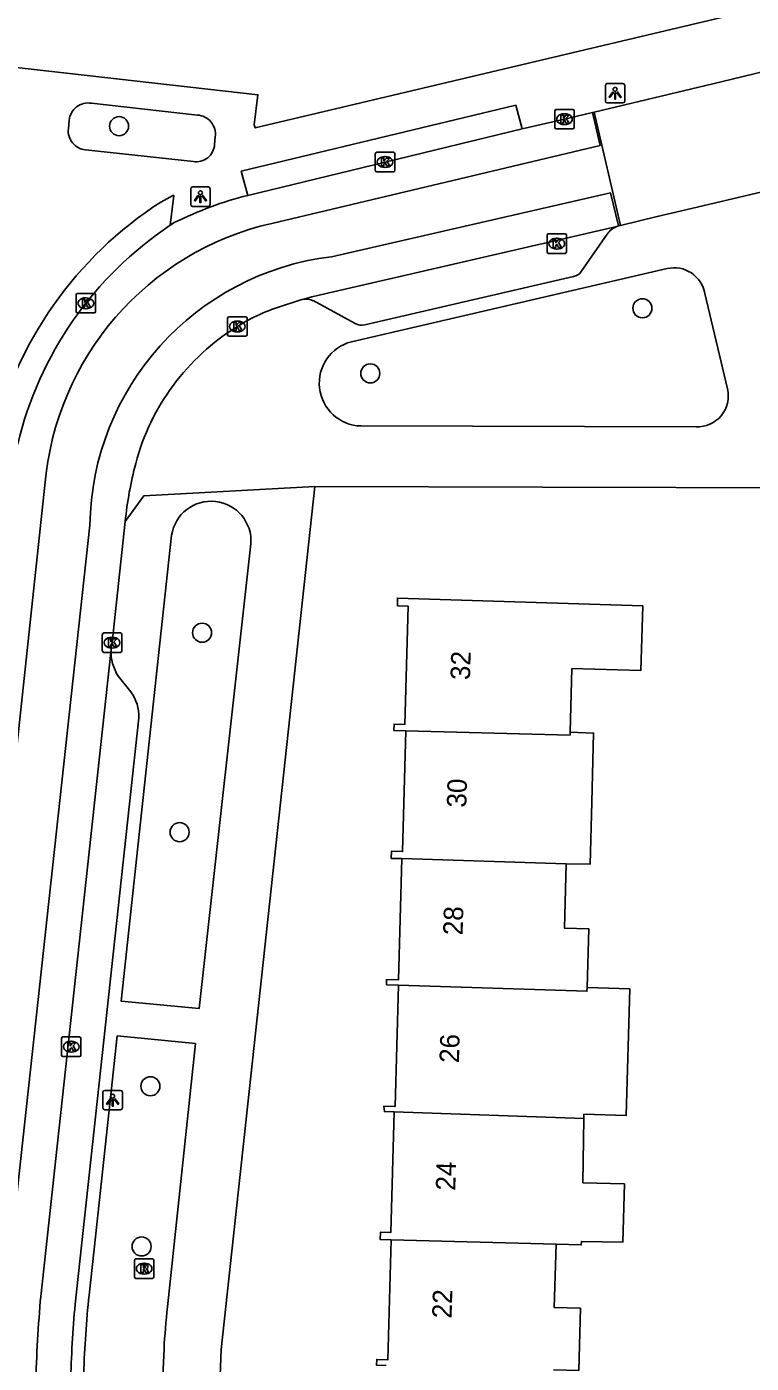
# Model space of a CAD drawing. Extents: x 162082 to 163393, y 388091 to 388632.
# Drawn here: x 162912.2 to 162949.4, y 388192.6 to 388261.2 of the extents above; entities that cross this region are included whole.
import ezdxf

# ---------------------------------------------------------------- set-up
doc = ezdxf.new("R2010")
doc.units = 0
for name, color, linetype in [('IMGEO_Boom', 7, 'Continuous'), ('IMGEO_Kolk', 7, 'Continuous'), ('IMGEO_Lichtpunt', 7, 'Continuous'), ('IMGEO_Muur', 7, 'Continuous'), ('IMGEO_Pand', 7, 'Continuous'), ('IMGEO_Pand_nummerreeks', 7, 'Continuous'), ('IMGEO_Rijbaan_lokaal_gesloten', 7, 'Continuous'), ('IMGEO_Rioolput', 7, 'Continuous'), ('IMGEO_Voetpad_open', 7, 'Continuous')]:
    doc.layers.add(name, color=color, linetype=linetype)

msp = doc.modelspace()

# ---------------------------------------------------------------- linework, layer by layer
at = {"layer": 'IMGEO_Boom'}
for centre in [(162916.912, 388256.097), (162943.781, 388246.745), (162929.812, 388243.401), (162921.173, 388230.086), (162920.021, 388219.843), (162918.519, 388206.794), (162918.07, 388198.567)]:
    msp.add_circle(centre, 0.489, dxfattribs=at)
at = {"layer": 'IMGEO_Kolk'}
for p, q in [((162939.28, 388256.031), (162939.28, 388256.883)), ((162939.355, 388256.957), (162940.207, 388256.957)), ((162939.768, 388256.737), (162939.793, 388256.737)), ((162940.281, 388256.883), (162940.281, 388256.031)), ((162940.207, 388255.957), (162939.355, 388255.957)), ((162939.791, 388256.177), (162939.766, 388256.177)), ((162930.068, 388253.829), (162930.068, 388254.681)), ((162930.143, 388254.755), (162930.995, 388254.755)), ((162930.556, 388254.535), (162930.581, 388254.535)), ((162931.069, 388254.681), (162931.069, 388253.829)), ((162930.995, 388253.755), (162930.143, 388253.755)), ((162930.579, 388253.975), (162930.554, 388253.975)), ((162938.886, 388249.64), (162938.886, 388250.492)), ((162938.961, 388250.566), (162939.813, 388250.566)), ((162939.374, 388250.346), (162939.399, 388250.346)), ((162939.887, 388250.492), (162939.887, 388249.64)), ((162939.813, 388249.566), (162938.961, 388249.566)), ((162939.397, 388249.786), (162939.372, 388249.786)), ((162914.78, 388247.503), (162915.632, 388247.503)), ((162914.705, 388246.577), (162914.705, 388247.429)), ((162915.193, 388247.283), (162915.218, 388247.283)), ((162915.706, 388247.429), (162915.706, 388246.577)), ((162915.632, 388246.503), (162914.78, 388246.503)), ((162915.216, 388246.723), (162915.191, 388246.723)), ((162922.482, 388245.384), (162922.482, 388246.236)), ((162922.557, 388246.31), (162923.409, 388246.31)), ((162923.483, 388246.236), (162923.483, 388245.384)), ((162922.993, 388245.53), (162922.968, 388245.53)), ((162922.97, 388246.09), (162922.995, 388246.09)), ((162923.409, 388245.31), (162922.557, 388245.31)), ((162916.051, 388229.148), (162916.051, 388230)), ((162916.126, 388230.074), (162916.978, 388230.074)), ((162916.539, 388229.854), (162916.564, 388229.854)), ((162917.052, 388230), (162917.052, 388229.148)), ((162916.978, 388229.074), (162916.126, 388229.074)), ((162916.562, 388229.294), (162916.537, 388229.294)), ((162913.954, 388208.399), (162913.954, 388209.251)), ((162914.029, 388209.325), (162914.881, 388209.325)), ((162914.442, 388209.105), (162914.467, 388209.105)), ((162914.955, 388209.251), (162914.955, 388208.399)), ((162914.465, 388208.545), (162914.44, 388208.545)), ((162914.881, 388208.325), (162914.029, 388208.325))]:
    msp.add_line(p, q, dxfattribs=at)
for points in [[(162939.28, 388256.031), (162939.28, 388256.883)], [(162939.355, 388256.957), (162940.207, 388256.957)], [(162939.601, 388256.657), (162939.724, 388256.657), (162939.724, 388256.506), (162939.854, 388256.657), (162940.018, 388256.657), (162939.872, 388256.506), (162940.025, 388256.257), (162939.873, 388256.257), (162939.788, 388256.421), (162939.724, 388256.354), (162939.724, 388256.257), (162939.601, 388256.257), (162939.601, 388256.657)], [(162940.281, 388256.883), (162940.281, 388256.031)], [(162940.207, 388255.957), (162939.355, 388255.957)], [(162930.068, 388253.829), (162930.068, 388254.681)], [(162930.143, 388254.755), (162930.995, 388254.755)], [(162930.389, 388254.455), (162930.512, 388254.455), (162930.512, 388254.304), (162930.642, 388254.455), (162930.806, 388254.455), (162930.66, 388254.304), (162930.813, 388254.055), (162930.661, 388254.055), (162930.576, 388254.219), (162930.512, 388254.152), (162930.512, 388254.055), (162930.389, 388254.055), (162930.389, 388254.455)], [(162931.069, 388254.681), (162931.069, 388253.829)], [(162930.995, 388253.755), (162930.143, 388253.755)], [(162938.886, 388249.64), (162938.886, 388250.492)], [(162938.961, 388250.566), (162939.813, 388250.566)], [(162939.207, 388250.266), (162939.33, 388250.266), (162939.33, 388250.115), (162939.46, 388250.266), (162939.624, 388250.266), (162939.478, 388250.115), (162939.631, 388249.866), (162939.479, 388249.866), (162939.394, 388250.03), (162939.33, 388249.963), (162939.33, 388249.866), (162939.207, 388249.866), (162939.207, 388250.266)], [(162939.887, 388250.492), (162939.887, 388249.64)], [(162939.813, 388249.566), (162938.961, 388249.566)], [(162914.78, 388247.503), (162915.632, 388247.503)], [(162914.705, 388246.577), (162914.705, 388247.429)], [(162915.026, 388247.203), (162915.149, 388247.203), (162915.149, 388247.052), (162915.279, 388247.203), (162915.443, 388247.203), (162915.297, 388247.052), (162915.45, 388246.803), (162915.298, 388246.803), (162915.213, 388246.967), (162915.149, 388246.9), (162915.149, 388246.803), (162915.026, 388246.803), (162915.026, 388247.203)], [(162915.706, 388247.429), (162915.706, 388246.577)], [(162915.632, 388246.503), (162914.78, 388246.503)], [(162922.482, 388245.384), (162922.482, 388246.236)], [(162922.557, 388246.31), (162923.409, 388246.31)], [(162923.483, 388246.236), (162923.483, 388245.384)], [(162922.803, 388246.01), (162922.926, 388246.01), (162922.926, 388245.859), (162923.056, 388246.01), (162923.22, 388246.01), (162923.074, 388245.859), (162923.227, 388245.61), (162923.075, 388245.61), (162922.99, 388245.774), (162922.926, 388245.707), (162922.926, 388245.61), (162922.803, 388245.61), (162922.803, 388246.01)], [(162923.409, 388245.31), (162922.557, 388245.31)], [(162916.051, 388229.148), (162916.051, 388230)], [(162916.126, 388230.074), (162916.978, 388230.074)], [(162916.372, 388229.774), (162916.495, 388229.774), (162916.495, 388229.623), (162916.625, 388229.774), (162916.789, 388229.774), (162916.643, 388229.623), (162916.796, 388229.374), (162916.644, 388229.374), (162916.559, 388229.538), (162916.495, 388229.471), (162916.495, 388229.374), (162916.372, 388229.374), (162916.372, 388229.774)], [(162917.052, 388230), (162917.052, 388229.148)], [(162916.978, 388229.074), (162916.126, 388229.074)], [(162913.954, 388208.399), (162913.954, 388209.251)], [(162914.029, 388209.325), (162914.881, 388209.325)], [(162914.955, 388209.251), (162914.955, 388208.399)], [(162914.275, 388209.025), (162914.398, 388209.025), (162914.398, 388208.874), (162914.528, 388209.025), (162914.692, 388209.025), (162914.546, 388208.874), (162914.699, 388208.625), (162914.547, 388208.625), (162914.462, 388208.789), (162914.398, 388208.722), (162914.398, 388208.625), (162914.275, 388208.625), (162914.275, 388209.025)], [(162914.881, 388208.325), (162914.029, 388208.325)]]:
    msp.add_lwpolyline(points, dxfattribs=at)
for centre, start, end in [((162939.357, 388256.881), 91.55205, 178.44795), ((162939.357, 388256.881), 91.55205, 178.44795), ((162940.205, 388256.881), 1.55205, 88.44795), ((162940.205, 388256.881), 1.55205, 88.44795), ((162939.357, 388256.033), 181.55205, 268.44795), ((162939.357, 388256.033), 181.55205, 268.44795), ((162940.205, 388256.033), 271.55205, 358.44795), ((162940.205, 388256.033), 271.55205, 358.44795), ((162930.145, 388254.679), 91.55205, 178.44795), ((162930.145, 388254.679), 91.55205, 178.44795), ((162930.993, 388254.679), 1.55205, 88.44795), ((162930.993, 388254.679), 1.55205, 88.44795), ((162930.145, 388253.831), 181.55205, 268.44795), ((162930.145, 388253.831), 181.55205, 268.44795), ((162930.993, 388253.831), 271.55205, 358.44795), ((162930.993, 388253.831), 271.55205, 358.44795), ((162938.963, 388250.49), 91.55205, 178.44795), ((162938.963, 388250.49), 91.55205, 178.44795), ((162939.811, 388250.49), 1.55205, 88.44795), ((162939.811, 388250.49), 1.55205, 88.44795), ((162938.963, 388249.642), 181.55205, 268.44795), ((162938.963, 388249.642), 181.55205, 268.44795), ((162939.811, 388249.642), 271.55205, 358.44795), ((162939.811, 388249.642), 271.55205, 358.44795), ((162914.782, 388247.427), 91.55205, 178.44795), ((162914.782, 388247.427), 91.55205, 178.44795), ((162915.63, 388247.427), 1.55205, 88.44795), ((162915.63, 388247.427), 1.55205, 88.44795), ((162914.782, 388246.579), 181.55205, 268.44795), ((162914.782, 388246.579), 181.55205, 268.44795), ((162915.63, 388246.579), 271.55205, 358.44795), ((162915.63, 388246.579), 271.55205, 358.44795), ((162922.559, 388246.234), 91.55205, 178.44795), ((162922.559, 388246.234), 91.55205, 178.44795), ((162923.407, 388246.234), 1.55205, 88.44795), ((162923.407, 388246.234), 1.55205, 88.44795), ((162922.559, 388245.386), 181.55205, 268.44795), ((162922.559, 388245.386), 181.55205, 268.44795), ((162923.407, 388245.386), 271.55205, 358.44795), ((162923.407, 388245.386), 271.55205, 358.44795), ((162916.128, 388229.998), 91.55205, 178.44795), ((162916.128, 388229.998), 91.55205, 178.44795), ((162916.976, 388229.998), 1.55205, 88.44795), ((162916.976, 388229.998), 1.55205, 88.44795), ((162916.128, 388229.15), 181.55205, 268.44795), ((162916.128, 388229.15), 181.55205, 268.44795), ((162916.976, 388229.15), 271.55205, 358.44795), ((162916.976, 388229.15), 271.55205, 358.44795), ((162914.031, 388209.249), 91.55205, 178.44795), ((162914.031, 388209.249), 91.55205, 178.44795), ((162914.879, 388209.249), 1.55205, 88.44795), ((162914.879, 388209.249), 1.55205, 88.44795), ((162914.031, 388208.401), 181.55205, 268.44795), ((162914.031, 388208.401), 181.55205, 268.44795), ((162914.879, 388208.401), 271.55205, 358.44795), ((162914.879, 388208.401), 271.55205, 358.44795)]:
    msp.add_arc(centre, 0.0765, start, end, dxfattribs=at)
for centre, major_axis, ratio, start_param, end_param in [((162939.767, 388256.457), (-0.387, 0.002), 0.722429, 4.712389, 7.853982), ((162939.792, 388256.457), (-0.39, 0.002), 0.717154, 1.570796, 4.712389), ((162930.555, 388254.255), (-0.387, 0.002), 0.722429, 4.712389, 7.853982), ((162930.58, 388254.255), (-0.39, 0.002), 0.717154, 1.570796, 4.712389), ((162939.373, 388250.066), (-0.387, 0.002), 0.722429, 4.712389, 7.853982), ((162939.398, 388250.066), (-0.39, 0.002), 0.717154, 1.570796, 4.712389), ((162915.192, 388247.003), (-0.387, 0.002), 0.722429, 4.712389, 7.853982), ((162915.217, 388247.003), (-0.39, 0.002), 0.717154, 1.570796, 4.712389), ((162922.969, 388245.81), (-0.387, 0.002), 0.722429, 4.712389, 7.853982), ((162922.994, 388245.81), (-0.39, 0.002), 0.717154, 1.570796, 4.712389), ((162916.538, 388229.574), (-0.387, 0.002), 0.722429, 4.712389, 7.853982), ((162916.563, 388229.574), (-0.39, 0.002), 0.717154, 1.570796, 4.712389), ((162914.441, 388208.825), (-0.387, 0.002), 0.722429, 4.712389, 7.853982), ((162914.466, 388208.825), (-0.39, 0.002), 0.717154, 1.570796, 4.712389)]:
    msp.add_ellipse(centre, major_axis=major_axis, ratio=ratio, start_param=start_param, end_param=end_param, dxfattribs=at)
at = {"layer": 'IMGEO_Lichtpunt'}
for p, q in [((162941.882, 388258.192), (162941.882, 388257.385)), ((162941.882, 388258.192), (162941.882, 388257.385)), ((162942.784, 388258.287), (162941.976, 388258.287)), ((162942.784, 388258.287), (162941.976, 388258.287)), ((162942.878, 388257.385), (162942.878, 388258.192)), ((162942.878, 388257.385), (162942.878, 388258.192)), ((162941.976, 388257.291), (162942.784, 388257.291)), ((162941.976, 388257.291), (162942.784, 388257.291)), ((162921.491, 388252.974), (162920.683, 388252.974)), ((162921.491, 388252.974), (162920.683, 388252.974)), ((162920.589, 388252.879), (162920.589, 388252.072)), ((162920.589, 388252.879), (162920.589, 388252.072)), ((162921.585, 388252.072), (162921.585, 388252.879)), ((162921.585, 388252.072), (162921.585, 388252.879)), ((162920.683, 388251.978), (162921.491, 388251.978)), ((162920.683, 388251.978), (162921.491, 388251.978)), ((162916.085, 388206.486), (162916.085, 388205.679)), ((162916.085, 388206.486), (162916.085, 388205.679)), ((162916.987, 388206.581), (162916.179, 388206.581)), ((162916.987, 388206.581), (162916.179, 388206.581)), ((162917.081, 388205.679), (162917.081, 388206.486)), ((162917.081, 388205.679), (162917.081, 388206.486)), ((162916.179, 388205.585), (162916.987, 388205.585)), ((162916.179, 388205.585), (162916.987, 388205.585))]:
    msp.add_line(p, q, dxfattribs=at)
for points in [[(162942.256, 388257.856), (162942.295, 388257.828), (162942.107, 388257.566), (162942.069, 388257.593), (162942.256, 388257.856)], [(162942.358, 388257.808), (162942.405, 388257.808), (162942.405, 388257.486), (162942.358, 388257.486), (162942.358, 388257.808)], [(162942.468, 388257.828), (162942.506, 388257.855), (162942.693, 388257.593), (162942.654, 388257.565), (162942.468, 388257.828)], [(162920.963, 388252.543), (162921.002, 388252.515), (162920.814, 388252.253), (162920.776, 388252.28), (162920.963, 388252.543)], [(162921.065, 388252.495), (162921.112, 388252.495), (162921.112, 388252.173), (162921.065, 388252.173), (162921.065, 388252.495)], [(162921.175, 388252.515), (162921.213, 388252.542), (162921.4, 388252.28), (162921.361, 388252.252), (162921.175, 388252.515)], [(162916.459, 388206.15), (162916.498, 388206.122), (162916.31, 388205.86), (162916.272, 388205.887), (162916.459, 388206.15)], [(162916.561, 388206.102), (162916.608, 388206.102), (162916.608, 388205.78), (162916.561, 388205.78), (162916.561, 388206.102)], [(162916.671, 388206.122), (162916.709, 388206.149), (162916.896, 388205.887), (162916.857, 388205.859), (162916.671, 388206.122)]]:
    msp.add_lwpolyline(points, dxfattribs=at)
for centre in [(162942.381, 388257.99), (162921.088, 388252.677), (162916.584, 388206.284)]:
    msp.add_circle(centre, 0.0994, dxfattribs=at)
for centre, start, end in [((162941.976, 388258.192), 90, 180), ((162941.976, 388258.192), 90, 180), ((162942.784, 388258.192), 0, 90), ((162942.784, 388258.192), 0, 90), ((162941.976, 388257.385), 180, 270), ((162941.976, 388257.385), 180, 270), ((162942.784, 388257.385), 270, 0), ((162942.784, 388257.385), 270, 360), ((162920.683, 388252.879), 90, 180), ((162920.683, 388252.879), 90, 180), ((162921.491, 388252.879), 0, 90), ((162921.491, 388252.879), 0, 90), ((162920.683, 388252.072), 180, 270), ((162920.683, 388252.072), 180, 270), ((162921.491, 388252.072), 270, 0), ((162921.491, 388252.072), 270, 360), ((162916.179, 388206.486), 90, 180), ((162916.179, 388206.486), 90, 180), ((162916.987, 388206.486), 0, 90), ((162916.987, 388206.486), 0, 90), ((162916.179, 388205.679), 180, 270), ((162916.179, 388205.679), 180, 270), ((162916.987, 388205.679), 270, 0), ((162916.987, 388205.679), 270, 360)]:
    msp.add_arc(centre, 0.0946, start, end, dxfattribs=at)
at = {"layer": 'IMGEO_Muur'}
msp.add_lwpolyline([(162938.65, 388237.56), (162952.361, 388237.528)], dxfattribs=at)
at = {"layer": 'IMGEO_Pand'}
for points in [[(162931.642, 388225.045), (162931.025, 388225.07), (162931.029, 388225.391), (162931.587, 388225.376), (162931.754, 388231.453), (162931.211, 388231.461), (162931.207, 388231.86), (162943.8, 388231.472), (162943.708, 388228.144), (162940.164, 388228.241), (162940.074, 388224.983)], [(162931.426, 388218.487), (162930.882, 388218.495), (162930.891, 388218.864), (162931.472, 388218.848), (162931.642, 388225.045)], [(162940.074, 388224.983), (162940.07, 388224.831), (162931.642, 388225.045)], [(162940.074, 388224.983), (162941.279, 388224.927), (162941.182, 388221.388), (162941.094, 388218.191), (162939.868, 388218.224)], [(162931.254, 388211.984), (162930.648, 388212.004), (162930.648, 388212.273), (162931.255, 388212.257), (162931.426, 388218.487)], [(162931.426, 388218.487), (162939.868, 388218.224)], [(162939.868, 388218.224), (162939.778, 388214.914), (162941.023, 388214.879), (162940.94, 388211.859)], [(162931.038, 388205.483), (162930.534, 388205.497), (162930.508, 388205.777), (162931.084, 388205.761), (162931.254, 388211.984)], [(162940.94, 388211.859), (162940.935, 388211.676), (162931.254, 388211.984)], [(162940.94, 388211.859), (162943.134, 388211.791), (162942.956, 388205.289), (162940.775, 388205.355), (162940.769, 388205.136)], [(162930.879, 388198.904), (162930.319, 388198.919), (162930.329, 388199.301), (162930.868, 388199.286), (162931.038, 388205.483)], [(162931.038, 388205.483), (162940.769, 388205.136)], [(162940.769, 388205.136), (162940.73, 388201.838), (162942.86, 388201.78), (162942.778, 388198.79), (162940.648, 388198.828), (162940.643, 388198.646), (162939.348, 388198.681)], [(162930.625, 388192.454), (162930.137, 388192.468), (162930.145, 388192.767), (162930.711, 388192.752), (162930.879, 388198.904)], [(162939.348, 388198.681), (162930.879, 388198.904)], [(162939.348, 388198.681), (162939.259, 388195.428), (162940.603, 388195.392), (162940.516, 388192.195), (162939.221, 388192.23)]]:
    msp.add_lwpolyline(points, dxfattribs=at)
at = {"layer": 'IMGEO_Rijbaan_lokaal_gesloten'}
for points in [[(162941.305, 388256.821), (162947.83, 388258.381), (162950.712, 388259.07)], [(162924.749, 388251.106), (162941.607, 388255.112), (162941.219, 388256.801)], [(162937.611, 388255.956), (162939.781, 388256.457), (162941.219, 388256.801)], [(162941.219, 388256.801), (162941.305, 388256.821)], [(162941.305, 388256.821), (162942.66, 388251.004)], [(162937.611, 388255.956), (162930.569, 388254.255), (162923.529, 388252.54)], [(162942.66, 388251.004), (162944.548, 388251.451), (162946.007, 388251.799), (162949.926, 388252.732), (162954.592, 388253.843)], [(162942.55, 388250.976), (162942.15, 388252.668), (162927.812, 388249.391)], [(162919.54, 388251.007), (162919.781, 388251.165)], [(162942.475, 388250.95), (162926.809, 388247.337), (162926.392, 388247.214)], [(162942.55, 388250.976), (162942.475, 388250.95)], [(162942.66, 388251.004), (162942.603, 388250.991), (162942.55, 388250.976)], [(162926.392, 388247.214), (162926.299, 388247.197), (162925.879, 388247.063), (162925.35, 388246.895)], [(162908.027, 388206.911), (162909.773, 388206.741), (162913.104, 388237.667)], [(162915.414, 388235.599), (162911.304, 388197.896)], [(162917.226, 388235.799), (162916.552, 388229.574), (162916.513, 388229.332), (162916.503, 388229.214)], [(162916.503, 388229.214), (162912.876, 388195.836), (162912.867, 388195.751)]]:
    msp.add_lwpolyline(points, dxfattribs=at)
for centre, radius, start, end in [((162928.143, 388234.168), 18.943, 104.09728, 116.19509), ((162929.916, 388235.429), 18.717, 123.66474, 166.59791), ((162928.125, 388236.416), 15.073, 102.94311, 175.23851), ((162929.508, 388235.398), 14.096, 96.91235, 179.1812), ((162928.355, 388237.214), 10.136, 107.24654, 122.00559), ((162929.196, 388235.745), 11.828, 121.68568, 165.14759), ((162936.937, 388233.782), 19.814, 165.39879, 174.15748), ((162980.265, 388189.981), 67.644, 175.1072, 178.99072)]:
    msp.add_arc(centre, radius, start, end, dxfattribs=at)
at = {"layer": 'IMGEO_Rioolput'}
for p, q in [((162917.698, 388197), (162917.698, 388197.852)), ((162917.773, 388197.926), (162918.625, 388197.926)), ((162918.186, 388197.706), (162918.211, 388197.706)), ((162918.699, 388197.852), (162918.699, 388197)), ((162918.625, 388196.926), (162917.773, 388196.926)), ((162918.209, 388197.146), (162918.184, 388197.146))]:
    msp.add_line(p, q, dxfattribs=at)
for points in [[(162917.698, 388197), (162917.698, 388197.852)], [(162917.773, 388197.926), (162918.625, 388197.926)], [(162918.287, 388197.624), (162918.035, 388197.626), (162918.035, 388197.226)], [(162918.035, 388197.226), (162918.159, 388197.226), (162918.159, 388197.388), (162918.17, 388197.388)], [(162918.213, 388197.545), (162918.159, 388197.545), (162918.159, 388197.464)], [(162918.159, 388197.464), (162918.211, 388197.464)], [(162918.699, 388197.852), (162918.699, 388197)], [(162918.625, 388196.926), (162917.773, 388196.926)], [(162918.217, 388197.359), (162918.288, 388197.226), (162918.428, 388197.226), (162918.363, 388197.352)]]:
    msp.add_lwpolyline(points, dxfattribs=at)
for centre, radius, start, end in [((162917.775, 388197.85), 0.0765, 91.55205, 178.44795), ((162917.775, 388197.85), 0.0765, 91.55205, 178.44795), ((162918.169, 388197.335), 0.0533, 26.02933, 88.69889), ((162918.195, 388197.653), 0.19, 274.7715, 282.96867), ((162918.219, 388197.449), 0.0964, 77.00612, 93.18647), ((162918.233, 388197.506), 0.0378, 276.66336, 79.67722), ((162918.286, 388197.514), 0.109, 350.36119, 89.41601), ((162918.284, 388197.514), 0.112, 277.58423, 350.98172), ((162918.268, 388197.299), 0.108, 29.51342, 73.79051), ((162918.623, 388197.85), 0.0765, 1.55205, 88.44795), ((162918.623, 388197.85), 0.0765, 1.55205, 88.44795), ((162917.775, 388197.002), 0.0765, 181.55205, 268.44795), ((162917.775, 388197.002), 0.0765, 181.55205, 268.44795), ((162918.623, 388197.002), 0.0765, 271.55205, 358.44795), ((162918.623, 388197.002), 0.0765, 271.55205, 358.44795)]:
    msp.add_arc(centre, radius, start, end, dxfattribs=at)
for centre, major_axis, ratio, start_param, end_param in [((162918.185, 388197.426), (-0.387, 0.002), 0.722429, 4.712389, 7.853982), ((162918.21, 388197.426), (-0.39, 0.002), 0.717154, 1.570796, 4.712389)]:
    msp.add_ellipse(centre, major_axis=major_axis, ratio=ratio, start_param=start_param, end_param=end_param, dxfattribs=at)
at = {"layer": 'IMGEO_Voetpad_open'}
for points in [[(162951.024, 388262.43), (162923.899, 388256.008), (162923.853, 388256.162), (162924.044, 388257.709), (162909.814, 388259.308), (162910.334, 388264.217), (162907.36, 388264.58)], [(162915.491, 388257.273), (162920.93, 388256.667)], [(162923.529, 388252.54), (162923.18, 388253.781), (162937.283, 388257.167), (162937.611, 388255.956)], [(162914.306, 388255.952), (162914.35, 388256.407)], [(162921.851, 388255.547), (162921.814, 388255.148)], [(162920.724, 388254.281), (162915.182, 388254.886)], [(162919.053, 388252.198), (162919.667, 388252.542), (162919.715, 388252.538), (162919.54, 388251.007)], [(162941.965, 388250.552), (162940.642, 388248.639)], [(162928.842, 388245.024), (162945.049, 388248.784)], [(162940.243, 388248.384), (162929.525, 388245.888)], [(162946.988, 388247.497), (162948.149, 388242.601)], [(162929.039, 388245.956), (162926.875, 388247.136)], [(162946.536, 388240.66), (162929.323, 388240.7)], [(162917.226, 388235.799), (162918.177, 388237.112), (162926.956, 388237.587)], [(162926.956, 388237.587), (162922.155, 388193.276), (162921.877, 388186.061)], [(162926.956, 388237.587), (162938.65, 388237.56), (162952.361, 388237.528)], [(162923.68, 388234.641), (162921.026, 388210.793), (162917.012, 388211.169), (162919.611, 388235.087)], [(162916.879, 388227.841), (162917.516, 388227.04)], [(162917.926, 388225.708), (162914.657, 388195.603)], [(162915.368, 388196.066), (162915.695, 388199.067), (162916.821, 388209.382), (162920.835, 388208.992)], [(162920.835, 388208.992), (162919.394, 388195.461)], [(162919.218, 388193.291), (162919.061, 388189.927)]]:
    msp.add_lwpolyline(points, dxfattribs=at)
for centre, radius, start, end in [((162915.326, 388256.305), 0.982, 80.33894, 174.05684), ((162920.876, 388255.684), 0.985, 352.03178, 86.83061), ((162915.271, 388255.852), 0.97, 174.08807, 264.73617), ((162920.875, 388255.21), 0.941, 260.78835, 356.21003), ((162929.811, 388235.481), 19.879, 122.76365, 167.1335), ((162942.888, 388249.895), 1.132, 111.3706, 144.5658), ((162940.205, 388248.883), 0.501, 274.35238, 330.81273), ((162945.407, 388247.219), 1.606, 9.98312, 102.8689), ((162926.5, 388246.351), 0.869, 64.48358, 97.16935), ((162929.39, 388246.695), 0.818, 244.5876, 279.48243), ((162929.389, 388242.896), 2.197, 104.41975, 268.27517), ((162946.613, 388242.236), 1.578, 267.18726, 13.35856), ((162921.637, 388234.789), 2.048, 355.842, 171.64765), ((162918.748, 388229.091), 2.248, 176.85715, 213.77311), ((162915.888, 388225.81), 2.04, 357.13873, 37.07882), ((162975.202, 388189.993), 60.142, 174.20419, 178.03298), ((162972.396, 388190.255), 57.986, 174.70824, 178.69075), ((162961.693, 388190.938), 42.54, 173.89681, 176.82943)]:
    msp.add_arc(centre, radius, start, end, dxfattribs=at)

# ---------------------------------------------------------------- texts
at = {"layer": 'IMGEO_Pand_nummerreeks'}
for s, p in [('32', (162934.926, 388227.642)), ('30', (162934.737, 388221.092)), ('28', (162934.549, 388214.537)), ('26', (162934.361, 388207.978)), ('24', (162934.172, 388201.423)), ('22', (162933.984, 388194.864))]:
    msp.add_text(s, height=1, rotation=88.35401, dxfattribs=at).set_placement(p)

doc.saveas('drawing.dxf')
